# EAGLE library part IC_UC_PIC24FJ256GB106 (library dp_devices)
16-Bit Flash Microcontroller with USB On-The-Go(OTG)
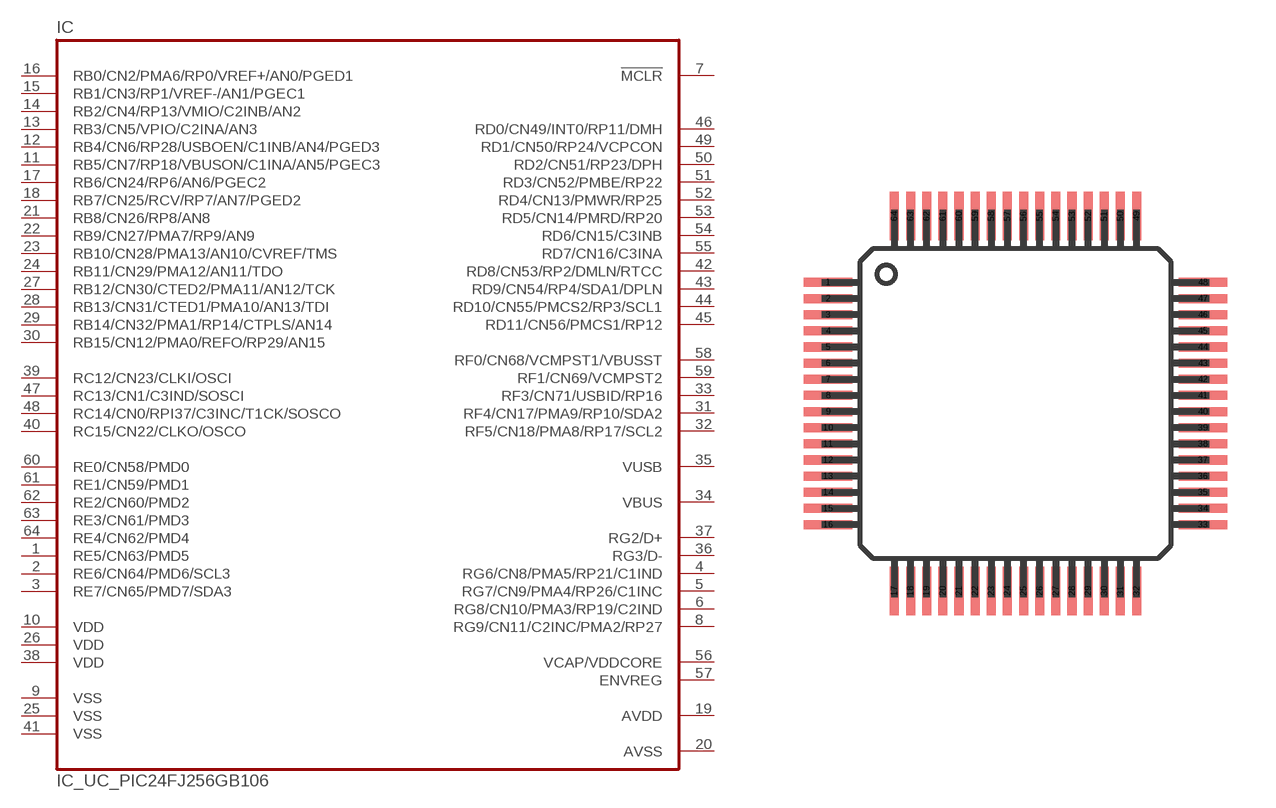
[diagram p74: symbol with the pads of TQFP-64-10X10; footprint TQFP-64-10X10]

Designator prefix IC

## IC_UC_PIC24FJ256GB106  [TQFP-64-10X10]
1  RE5/CN63/PMD5
2  RE6/CN64/PMD6/SCL3
3  RE7/CN65/PMD7/SDA3
4  RG6/CN8/PMA5/RP21/C1IND
5  RG7/CN9/PMA4/RP26/C1INC
6  RG8/CN10/PMA3/RP19/C2IND
7  !MCLR  in
8  RG9/CN11/C2INC/PMA2/RP27
9  VSS  pwr
10  VDD  pwr
11  RB5/CN7/RP18/VBUSON/C1INA/AN5/PGEC3
12  RB4/CN6/RP28/USBOEN/C1INB/AN4/PGED3
13  RB3/CN5/VPIO/C2INA/AN3
14  RB2/CN4/RP13/VMIO/C2INB/AN2
15  RB1/CN3/RP1/VREF-/AN1/PGEC1
16  RB0/CN2/PMA6/RP0/VREF+/AN0/PGED1
17  RB6/CN24/RP6/AN6/PGEC2
18  RB7/CN25/RCV/RP7/AN7/PGED2
19  AVDD  pwr
20  AVSS  pwr
21  RB8/CN26/RP8/AN8
22  RB9/CN27/PMA7/RP9/AN9
23  RB10/CN28/PMA13/AN10/CVREF/TMS
24  RB11/CN29/PMA12/AN11/TDO
25  VSS  pwr
26  VDD  pwr
27  RB12/CN30/CTED2/PMA11/AN12/TCK
28  RB13/CN31/CTED1/PMA10/AN13/TDI
29  RB14/CN32/PMA1/RP14/CTPLS/AN14
30  RB15/CN12/PMA0/REFO/RP29/AN15
31  RF4/CN17/PMA9/RP10/SDA2
32  RF5/CN18/PMA8/RP17/SCL2
33  RF3/CN71/USBID/RP16
34  VBUS
35  VUSB
36  RG3/D-
37  RG2/D+
38  VDD  pwr
39  RC12/CN23/CLKI/OSCI
40  RC15/CN22/CLKO/OSCO
41  VSS  pwr
42  RD8/CN53/RP2/DMLN/RTCC
43  RD9/CN54/RP4/SDA1/DPLN
44  RD10/CN55/PMCS2/RP3/SCL1
45  RD11/CN56/PMCS1/RP12
46  RD0/CN49/INT0/RP11/DMH
47  RC13/CN1/C3IND/SOSCI
48  RC14/CN0/RPI37/C3INC/T1CK/SOSCO
49  RD1/CN50/RP24/VCPCON
50  RD2/CN51/RP23/DPH
51  RD3/CN52/PMBE/RP22
52  RD4/CN13/PMWR/RP25
53  RD5/CN14/PMRD/RP20
54  RD6/CN15/C3INB
55  RD7/CN16/C3INA
56  VCAP/VDDCORE
57  ENVREG
58  RF0/CN68/VCMPST1/VBUSST
59  RF1/CN69/VCMPST2
60  RE0/CN58/PMD0
61  RE1/CN59/PMD1
62  RE2/CN60/PMD2
63  RE3/CN61/PMD3
64  RE4/CN62/PMD4

## Footprint TQFP-64-10X10 (pad centres in mm)
smd 1.5 x 0.28: 1 -5.8,3.75; 2 -5.8,3.25; 3 -5.8,2.75; 4 -5.8,2.25; 5 -5.8,1.75; 6 -5.8,1.25; 7 -5.8,0.75; 8 -5.8,0.25; 9 -5.8,-0.25; 10 -5.8,-0.75; 11 -5.8,-1.25; 12 -5.8,-1.75; 13 -5.8,-2.25; 14 -5.8,-2.75; 15 -5.8,-3.25; 16 -5.8,-3.75; 33 5.8,-3.75; 34 5.8,-3.25; 35 5.8,-2.75; 36 5.8,-2.25; 37 5.8,-1.75; 38 5.8,-1.25; 39 5.8,-0.75; 40 5.8,-0.25; 41 5.8,0.25; 42 5.8,0.75; 43 5.8,1.25; 44 5.8,1.75; 45 5.8,2.25; 46 5.8,2.75; 47 5.8,3.25; 48 5.8,3.75
smd 0.28 x 1.5: 17 -3.75,-5.8; 18 -3.25,-5.8; 19 -2.75,-5.8; 20 -2.25,-5.8; 21 -1.75,-5.8; 22 -1.25,-5.8; 23 -0.75,-5.8; 24 -0.25,-5.8; 25 0.25,-5.8; 26 0.75,-5.8; 27 1.25,-5.8; 28 1.75,-5.8; 29 2.25,-5.8; 30 2.75,-5.8; 31 3.25,-5.8; 32 3.75,-5.8; 49 3.75,5.8; 50 3.25,5.8; 51 2.75,5.8; 52 2.25,5.8; 53 1.75,5.8; 54 1.25,5.8; 55 0.75,5.8; 56 0.25,5.8; 57 -0.25,5.8; 58 -0.75,5.8; 59 -1.25,5.8; 60 -1.75,5.8; 61 -2.25,5.8; 62 -2.75,5.8; 63 -3.25,5.8; 64 -3.75,5.8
